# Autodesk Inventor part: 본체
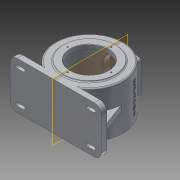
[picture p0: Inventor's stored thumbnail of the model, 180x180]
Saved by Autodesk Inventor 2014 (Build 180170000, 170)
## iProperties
Created: 2015-06
Part Number: 본체
Material: Aluminum 6061
Document SubType Name: Modeling
Designer: user
Density: 2.71 g/cm^3
Appearance: Aluminum - Flat
Mass: 3274.55 g
Surface Area: 2341.75 cm^2
Volume: 1208.32 cm^3
Author: user
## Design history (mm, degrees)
sketch "Sketch2"
  geometry: C1 r 85 at (0, 0); 1 further point
  constraints: 1 centre point, 1 coincident
extrude "Extrusion2" new body sketch "Sketch2" distance "d6" = 118; taper "d7" = 0 deg
workplane "Work Plane1"
sketch "Sketch3"
  geometry: L1 (115, 118)-(-115, 118); L2 (-115, 118)-(-115, 0); L3 (-115, 0)-(115, 0); L4 (115, 0)-(115, 118); 2 further points
  constraints: 8 end point, 1 coincident, 1 midpoint
  dimensions: "d9" = 230 distance of L2.end L3.end; "d10" = 118 distance of L1.end L2.end; "d11" = 115 distance from line of point (0, 0) L4
extrude "Extrusion3" join sketch "Sketch3" distance "d12" = 14; taper "d13" = 0 deg
workplane "Work Plane2"
sketch "Sketch4"
  geometry: L1 (-42.5, 101.5)-(42.5, 101.5); L2 (42.5, 101.5)-(42.5, 16.5); L3 (42.5, 16.5)-(-42.5, 16.5); L4 (-42.5, 16.5)-(-42.5, 101.5); L5 (-42.5, 101.5)-(42.5, 16.5); L6 (42.5, 101.5)-(-42.5, 16.5); L7 (85, 118)-(-85, 118) reference; L8 (-115, 118)-(-115, 0) reference; 4 further points
  constraints: 12 end point, 2 horizontal, 2 midpoint, 2 vertical
  dimensions: "d15" = 85 distance of L1.end L2.end; "d16" = 85 distance of L2.end L3.end; "d17" = 59 distance from line of point (0, 59) L7; "d18" = 115 distance from line of point (0, 59) L8
extrude "Extrusion4" join sketch "Sketch4" stored distance "d19" = 14; taper "d20" = 0 deg
sketch "Sketch5"
  geometry: C1 r 65 at (0, 0); A1 r 85 centre (0, 0) between (46.733, -71) and (-46.733, -71) reference
  constraints: 1 centre point, 1 coincident
extrude "Extrusion5" join sketch "Sketch5" distance "d21" = 13; taper "d22" = 0 deg
sketch "Sketch6"
  geometry: L1 (0, 11.5)-(29.368, 11.5); L2 (29.368, 11.5)-(31, 8); L3 (31, 8)-(77, 8); L4 (77, 8)-(77, 110); L5 (77, 110)-(0, 110); L6 (0, 110)-(0, 11.5); L7 (-71, 0)-(85, 0) reference; L8 (85, 118)-(-71, 118) reference; L9 (22.388, 11.5)-(0, 11.5); 1 further point
  constraints: 14 end point, 2 point on line
  dimensions: "d23" = 115 deg angle of L2 L3; "d24" = 102 distance of L3.end L4.end; "d25" = 77 distance between parallel lines of L6 L4; "d26" = 31 horizontal distance of point (0, 0) L2.end; "d27" = 8 distance between parallel lines of L3 L7; "d28" = 8 distance between parallel lines of L8 L5; "d29" = 3.5 distance between parallel lines of L1 L3
revolve "Revolution1" sketch "Sketch6" stored, may be unused: angle "d30" = 90 deg
sketch "Sketch7"
  geometry: C1 r 65 at (0, 0); A1 r 85 centre (0, 0) between (46.733, -71) and (-46.733, -71) reference
  constraints: 1 centre point, 1 coincident
extrude "Extrusion6" join sketch "Sketch7" distance "d31" = 3; taper "d32" = 0 deg
sketch "Sketch8"
  geometry: C1 r 65 at (0, 0) reference; C2 r 47.5 at (0, 0)
  constraints: 1 centre point, 1 coincident
extrude "Extrusion7" cut sketch "Sketch8" distance "d33" = 44.25; taper "d34" = 0 deg
sketch "Sketch9"
  geometry: C1 r 29.368 at (0, 0) reference; C2 r 23.5 at (0, 0)
  constraints: 1 centre point, 1 coincident
  dimensions: "d39" = 47 diameter of C2
extrude "Extrusion8" cut sketch "Sketch9" distance "d40" = 14; taper "d41" = 0 deg
sketch "Sketch10"
  geometry: C1 r 23.5 at (0, 0) reference; C2 r 15 at (0, 0)
  constraints: 1 centre point, 1 coincident
extrude "Extrusion9" cut sketch "Sketch10" distance "d42" = 3; taper "d43" = 0 deg
sketch "Sketch11"
  geometry: C1 r 35 at (0, -59); 1 further point
  constraints: 1 centre point
extrude "Extrusion10" cut sketch "Sketch11" distance "d44" = 58.25; taper "d45" = 0 deg
sketch "Sketch12"
  geometry: L1 (-35.5, -23.5)-(35.5, -23.5); L2 (35.5, -23.5)-(35.5, -94.5); L3 (35.5, -94.5)-(-35.5, -94.5); L4 (-35.5, -94.5)-(-35.5, -23.5); C1 r 35 at (0, -59) reference; 5 further points
  constraints: 8 end point, 4 coincident, 2 horizontal, 2 vertical
  dimensions: "d46" = 71 distance of L1.start L1.end; "d47" = 71 distance of L1.end L2.end; "d48" = 35.5 distance from line of C1.centre L1; "d49" = 35.5 distance from line of L2 C1.centre
hole "Hole1" sketch "Sketch12" at (-35.5, -23.5), (-35.5, -94.5), (35.5, -94.5), (35.5, -23.5) diameter "d50" = 3.242; stored, may be unused: countersink angle "d54" = 90 deg, drill point angle "d56" = 118 deg; dims "d51" = 10, "d52" = 47, "d53" = 14, "d55" = 13
workplane "Work Plane3"
sketch "Sketch13"
  geometry: L1 (-84.87, -4.703)-(-109, -71); L2 (-115, -85)-(-115, -71) reference; L3 (-46.733, -71)-(-115, -71) reference; L4 (84.87, -4.703)-(109, -71); L5 (115, -85)-(115, -71) reference; L6 (115, -71)-(46.733, -71) reference; A1 r 85 centre (0, 0) between (46.733, -71) and (-46.733, -71) reference; 1 further point
  constraints: 4 end point, 2 point on circle, 2 point on line
  dimensions: "d60" = 6 distance of L1.end L2.end; "d61" = 110 deg angle of L1 L3; "d62" = 6 distance from line of L5 L4.end; "d63" = 110 deg angle of L6 L4
feature "Rib1" sketch "Sketch13" dims "d64" = 1, "d65" = 15, "d66" = 0, "d67" = 0, "d68" = 1, "d69" = 1
mirror "Mirror1"
sketch "Sketch14"
  geometry: L1 (62.267, 0)-(0, 0) reference; L2 (0, 0)-(24.13, 66.297) reference; A1 r 85 centre (109, 71) between (24.13, 66.297) and (62.267, 0) reference
sketch "Sketch15"
  geometry: L1 (115, -118)-(115, 0) reference; L2 (81, -27)-(97, -27); L3 (97, -9)-(81, -9); L4 (-115, 0)-(-115, -118) reference; L5 (-115, -59)-(115, -59); A1 r 9 centre (81, -18) between (81, -9) and (81, -27); A2 r 9 centre (97, -18) between (97, -27) and (97, -9); 1 further point
  constraints: 6 end point, 4 point on circle, 2 centre point, 2 horizontal, 2 midpoint
  dimensions: "d70" = 18 diameter of A2; "d71" = 18 diameter of A1; "d72" = 16 distance of A2.centre A1.centre; "d73" = 97 horizontal distance of A2.centre point (0, 0); "d74" = 82 diameter of A2.centre L5; "d75" = 82 diameter of A1.centre L5
extrude "Extrusion11" join sketch "Sketch15" distance "d76" = 3; taper "d77" = 0 deg
sketch "Sketch16"
  geometry: L1 (81, -27)-(97, -27) reference; L2 (97, -9)-(81, -9) reference; L3 (81, -22)-(97, -22); L4 (97, -14)-(81, -14); A1 r 9 centre (81, -18) between (81, -9) and (81, -27) reference; A2 r 9 centre (97, -18) between (97, -27) and (97, -9) reference; A3 r 4 centre (81, -18) between (81, -14) and (81, -22); A4 r 4 centre (97, -18) between (97, -22) and (97, -14); 1 further point
  constraints: 4 end point, 4 point on circle, 2 centre point, 3 other
  dimensions: "d78" = 5 distance between parallel lines of L4 L2
extrude "Extrusion12" cut sketch "Sketch16" stored distance "d79" = 3; taper "d80" = 0 deg
mirror "Mirror2"
mirror "Mirror3"
workplane "Work Plane4"
workplane "Work Plane5"
sketch "Sketch17"
  geometry: L1 (-84.098, 0)-(85, 0) reference; 3 further points
  constraints: 1 other
  dimensions: "d82" = 59 distance from line of L1 point (0.451, 59)
emboss "Emboss1" sketch "Sketch17" dims "d84" = 0.5, "d85" = 0
fillet "Fillet1" dims "d86" = 7
fillet "Fillet2" dims "d87" = 3
fillet "Fillet3" dims "d88" = 18
fillet "Fillet4" dims "d89" = 3
fillet "Fillet5" dims "d90" = 3
chamfer "Chamfer1" distance "d91" = 1; stored, may be unused: second distance "d92" = 2, angle "d93" = 45 deg
fillet "Fillet6" dims "d94" = 0.3
sketch "Sketch19"
  geometry: C1 r 48.5 at (0, 0) reference; A1 r 55 centre (0, 0) between (0, 55) and (55, 0); 2 further points
  constraints: 4 point on circle, 1 centre point, 1 coincident
hole "Hole2" sketch "Sketch19" at (-55, 0), (0, 55), (55, 0), (0, -55) diameter "d95" = 3.242; stored, may be unused: countersink angle "d99" = 90 deg, drill point angle "d101" = 118 deg; dims "d96" = 3, "d97" = 4, "d98" = 2, "d100" = 27.25
body "Solid2"
other parameters: "d8" = -85, "d14" = 173, "d81" = 65 deg
